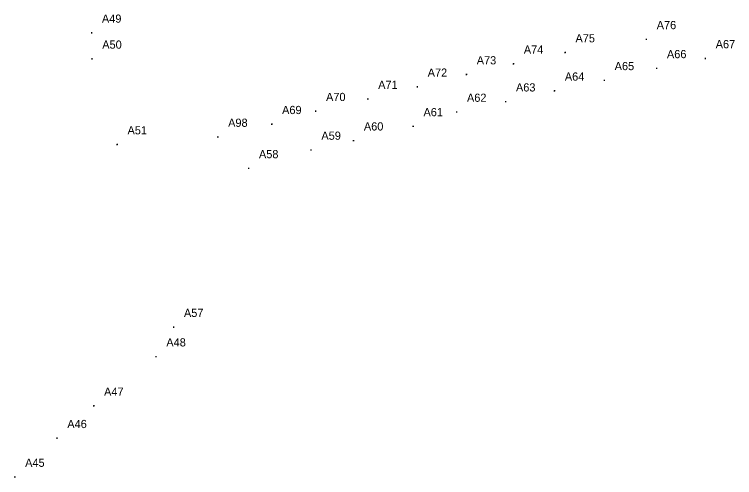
# Model space of a CAD drawing. Extents: x 1727960 to 1749562, y 651707 to 653731.
# Drawn here: x 1747364.6 to 1747716.5, y 652401.1 to 652627.3 of the extents above; entities that cross this region are included whole.
import ezdxf

# ---------------------------------------------------------------- set-up
doc = ezdxf.new("R2010")
doc.units = 0
doc.layers.add('SURVEY - DRAINAGE - Storm Sewer - Points - Locators', color=7, linetype='Continuous')
doc.layers.add('SURVEY - DRAINAGE - Storm Sewer - Points - Numbers', color=7, linetype='Continuous')

msp = doc.modelspace()

# ---------------------------------------------------------------- linework, layer by layer
at = {"layer": 'SURVEY - DRAINAGE - Storm Sewer - Points - Locators'}
for p, q in [((1747402.57, 652618.23), (1747402.07, 652618.23)), ((1747402.32, 652617.98), (1747402.32, 652618.48)), ((1747402.32, 652618.23), (1747402.32, 652618.23)), ((1747402.32, 652618.23), (1747402.32, 652618.23)), ((1747673.64, 652615.08), (1747673.14, 652615.08)), ((1747673.39, 652614.83), (1747673.39, 652615.33)), ((1747673.39, 652615.08), (1747673.39, 652615.08)), ((1747673.39, 652615.08), (1747673.39, 652615.08)), ((1747633.96, 652608.63), (1747633.46, 652608.63)), ((1747633.71, 652608.38), (1747633.71, 652608.88)), ((1747633.71, 652608.63), (1747633.71, 652608.63)), ((1747633.71, 652608.63), (1747633.71, 652608.63)), ((1747402.73, 652605.55), (1747402.23, 652605.55)), ((1747402.48, 652605.3), (1747402.48, 652605.8)), ((1747402.48, 652605.55), (1747402.48, 652605.55)), ((1747402.48, 652605.55), (1747402.48, 652605.55)), ((1747702.46, 652605.75), (1747701.96, 652605.75)), ((1747702.21, 652605.5), (1747702.21, 652606)), ((1747702.21, 652605.75), (1747702.21, 652605.75)), ((1747702.21, 652605.75), (1747702.21, 652605.75)), ((1747608.71, 652603.12), (1747608.21, 652603.12)), ((1747608.46, 652602.87), (1747608.46, 652603.37)), ((1747608.46, 652603.12), (1747608.46, 652603.12)), ((1747608.46, 652603.12), (1747608.46, 652603.12)), ((1747678.65, 652600.9), (1747678.15, 652600.9)), ((1747678.4, 652600.65), (1747678.4, 652601.15)), ((1747678.4, 652600.9), (1747678.4, 652600.9)), ((1747678.4, 652600.9), (1747678.4, 652600.9)), ((1747585.71, 652597.88), (1747585.21, 652597.88)), ((1747585.46, 652597.63), (1747585.46, 652598.13)), ((1747585.46, 652597.88), (1747585.46, 652597.88)), ((1747585.46, 652597.88), (1747585.46, 652597.88)), ((1747653.1, 652595.07), (1747652.6, 652595.07)), ((1747652.85, 652594.82), (1747652.85, 652595.32)), ((1747652.85, 652595.07), (1747652.85, 652595.07)), ((1747652.85, 652595.07), (1747652.85, 652595.07)), ((1747561.74, 652591.86), (1747561.24, 652591.86)), ((1747561.49, 652591.61), (1747561.49, 652592.11)), ((1747561.49, 652591.86), (1747561.49, 652591.86)), ((1747561.49, 652591.86), (1747561.49, 652591.86)), ((1747628.76, 652589.93), (1747628.26, 652589.93)), ((1747628.51, 652589.68), (1747628.51, 652590.18)), ((1747628.51, 652589.93), (1747628.51, 652589.93)), ((1747628.51, 652589.93), (1747628.51, 652589.93)), ((1747537.55, 652585.92), (1747537.05, 652585.92)), ((1747537.3, 652585.67), (1747537.3, 652586.17)), ((1747537.3, 652585.92), (1747537.3, 652585.92)), ((1747537.3, 652585.92), (1747537.3, 652585.92)), ((1747604.88, 652584.64), (1747604.38, 652584.64)), ((1747604.63, 652584.39), (1747604.63, 652584.89)), ((1747604.63, 652584.64), (1747604.63, 652584.64)), ((1747604.63, 652584.64), (1747604.63, 652584.64)), ((1747512.08, 652579.97), (1747511.58, 652579.97)), ((1747511.83, 652579.72), (1747511.83, 652580.22)), ((1747511.83, 652579.97), (1747511.83, 652579.97)), ((1747511.83, 652579.97), (1747511.83, 652579.97)), ((1747580.94, 652579.59), (1747580.44, 652579.59)), ((1747580.69, 652579.34), (1747580.69, 652579.84)), ((1747580.69, 652579.59), (1747580.69, 652579.59)), ((1747580.69, 652579.59), (1747580.69, 652579.59)), ((1747490.6, 652573.61), (1747490.1, 652573.61)), ((1747490.35, 652573.36), (1747490.35, 652573.86)), ((1747490.35, 652573.61), (1747490.35, 652573.61)), ((1747490.35, 652573.61), (1747490.35, 652573.61)), ((1747559.69, 652572.56), (1747559.19, 652572.56)), ((1747559.44, 652572.31), (1747559.44, 652572.81)), ((1747559.44, 652572.56), (1747559.44, 652572.56)), ((1747559.44, 652572.56), (1747559.44, 652572.56)), ((1747464.23, 652567.38), (1747463.73, 652567.38)), ((1747463.98, 652567.13), (1747463.98, 652567.63)), ((1747463.98, 652567.38), (1747463.98, 652567.38)), ((1747463.98, 652567.38), (1747463.98, 652567.38)), ((1747530.57, 652565.58), (1747530.07, 652565.58)), ((1747530.32, 652565.33), (1747530.32, 652565.83)), ((1747530.32, 652565.58), (1747530.32, 652565.58)), ((1747530.32, 652565.58), (1747530.32, 652565.58)), ((1747415.06, 652563.69), (1747414.56, 652563.69)), ((1747414.81, 652563.44), (1747414.81, 652563.94)), ((1747414.81, 652563.69), (1747414.81, 652563.69)), ((1747414.81, 652563.69), (1747414.81, 652563.69)), ((1747509.54, 652560.81), (1747509.54, 652561.31)), ((1747509.79, 652561.06), (1747509.29, 652561.06)), ((1747509.54, 652561.06), (1747509.54, 652561.06)), ((1747509.54, 652561.06), (1747509.54, 652561.06)), ((1747479.3, 652552.05), (1747478.8, 652552.05)), ((1747479.05, 652551.8), (1747479.05, 652552.3)), ((1747479.05, 652552.05), (1747479.05, 652552.05)), ((1747479.05, 652552.05), (1747479.05, 652552.05)), ((1747442.64, 652474.52), (1747442.14, 652474.52)), ((1747442.39, 652474.27), (1747442.39, 652474.77)), ((1747442.39, 652474.52), (1747442.39, 652474.52)), ((1747442.39, 652474.52), (1747442.39, 652474.52)), ((1747434.04, 652460.1), (1747433.54, 652460.1)), ((1747433.79, 652459.85), (1747433.79, 652460.35)), ((1747433.79, 652460.1), (1747433.79, 652460.1)), ((1747433.79, 652460.1), (1747433.79, 652460.1)), ((1747403.62, 652436.02), (1747403.12, 652436.02)), ((1747403.37, 652435.77), (1747403.37, 652436.27)), ((1747403.37, 652436.02), (1747403.37, 652436.02)), ((1747403.37, 652436.02), (1747403.37, 652436.02)), ((1747385.4, 652419.98), (1747385.4, 652420.48)), ((1747385.65, 652420.23), (1747385.15, 652420.23)), ((1747385.4, 652420.23), (1747385.4, 652420.23)), ((1747385.4, 652420.23), (1747385.4, 652420.23)), ((1747365.05, 652401.3), (1747364.55, 652401.3)), ((1747364.8, 652401.05), (1747364.8, 652401.55)), ((1747364.8, 652401.3), (1747364.8, 652401.3)), ((1747364.8, 652401.3), (1747364.8, 652401.3))]:
    msp.add_line(p, q, dxfattribs=at)

# ---------------------------------------------------------------- texts
at = {"layer": 'SURVEY - DRAINAGE - Storm Sewer - Points - Numbers'}
for s, p in [('A49', (1747407.32, 652623.23)), ('A76', (1747678.39, 652620.08)), ('A75', (1747638.71, 652613.63)), ('A50', (1747407.48, 652610.55)), ('A67', (1747707.21, 652610.75)), ('A74', (1747613.46, 652608.12)), ('A73', (1747590.46, 652602.88)), ('A66', (1747683.4, 652605.9)), ('A65', (1747657.85, 652600.07)), ('A72', (1747566.49, 652596.86)), ('A64', (1747633.51, 652594.93)), ('A71', (1747542.3, 652590.92)), ('A63', (1747609.63, 652589.64)), ('A70', (1747516.83, 652584.97)), ('A62', (1747585.69, 652584.59)), ('A69', (1747495.35, 652578.61)), ('A61', (1747564.44, 652577.56)), ('A98', (1747468.98, 652572.38)), ('A51', (1747419.81, 652568.69)), ('A60', (1747535.32, 652570.58)), ('A59', (1747514.54, 652566.06)), ('A58', (1747484.05, 652557.05)), ('A57', (1747447.39, 652479.52)), ('A48', (1747438.79, 652465.1)), ('A47', (1747408.37, 652441.02)), ('A46', (1747390.4, 652425.23)), ('A45', (1747369.8, 652406.3))]:
    msp.add_text(s, height=4, dxfattribs=at).set_placement(p)

doc.saveas('drawing.dxf')
